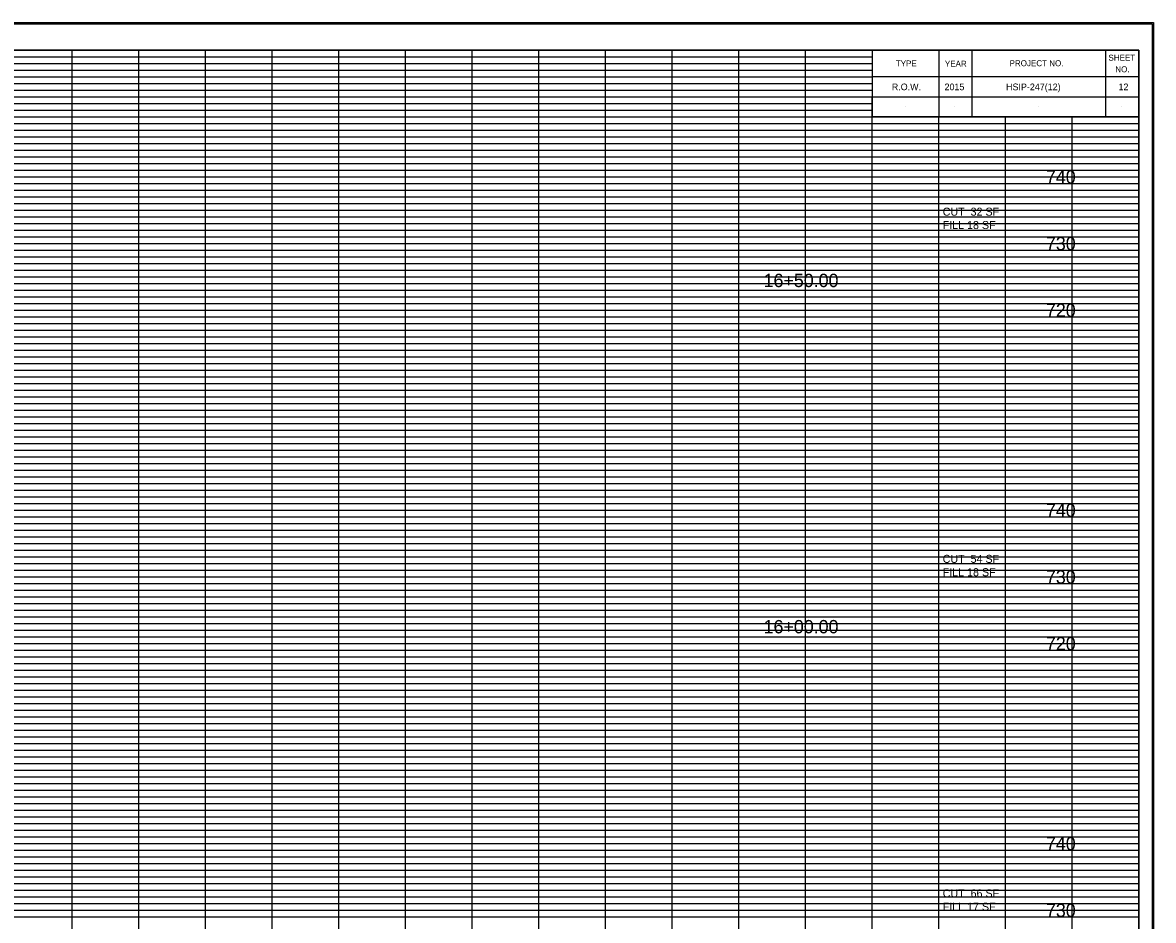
# Model space of a CAD drawing. Extents: x -200 to 1704, y -325 to 2307.
# Drawn here: x 1152.6 to 1322.2, y 1619.5 to 1754.1 of the extents above; entities that cross this region are included whole.
import ezdxf

# ---------------------------------------------------------------- set-up
doc = ezdxf.new("R2010")
doc.units = 0
for name, color, linetype in [('DESIGN - SCRATCH - User 1', 7, 'Continuous'), ('DESIGN - SHEET - Corner Text', 7, 'Continuous'), ('DESIGN - SHEET - Light Grid', 7, 'Continuous'), ('DESIGN - SHEET - Linework', 7, 'Continuous'), ('DESIGN - SHEET - Plot Shape', 7, 'Continuous'), ('DESIGN - TYPICAL - Text', 7, 'Continuous')]:
    doc.layers.add(name, color=color, linetype=linetype)

msp = doc.modelspace()

# ---------------------------------------------------------------- linework, layer by layer
at = {"layer": 'DESIGN - SCRATCH - User 1'}
for p, q in [((1285, 1744.5), (1285, 1744.5)), ((1292.4, 1744.5), (1292.4, 1744.5)), ((1304.9, 1744.5), (1304.9, 1744.5)), ((1317.4, 1744.5), (1317.4, 1744.5)), ((1285, 1741.5), (1285, 1741.5)), ((1292.4, 1741.5), (1292.4, 1741.5)), ((1304.9, 1741.5), (1304.9, 1741.5)), ((1317.4, 1741.5), (1317.4, 1741.5))]:
    msp.add_line(p, q, dxfattribs=at)
at = {"layer": 'DESIGN - SHEET - Light Grid'}
for p, q in [((1080, 1749), (1160, 1749)), ((1160, 1749), (1240, 1749)), ((1240, 1749), (1280, 1749)), ((1080, 1748), (1160, 1748)), ((1080, 1747), (1160, 1747)), ((1160, 1748), (1240, 1748)), ((1160, 1747), (1240, 1747)), ((1240, 1748), (1280, 1748)), ((1240, 1747), (1280, 1747)), ((1080, 1746), (1160, 1746)), ((1080, 1745), (1160, 1745)), ((1160, 1746), (1240, 1746)), ((1160, 1745), (1240, 1745)), ((1240, 1746), (1280, 1746)), ((1240, 1745), (1280, 1745)), ((1080, 1744), (1160, 1744)), ((1160, 1744), (1240, 1744)), ((1240, 1744), (1280, 1744)), ((1080, 1743), (1160, 1743)), ((1080, 1742), (1160, 1742)), ((1160, 1743), (1240, 1743)), ((1160, 1742), (1240, 1742)), ((1240, 1743), (1280, 1743)), ((1240, 1742), (1280, 1742)), ((1080, 1741), (1160, 1741)), ((1160, 1741), (1240, 1741)), ((1240, 1741), (1280, 1741)), ((1080, 1739), (1160, 1739)), ((1160, 1739), (1240, 1739)), ((1240, 1739), (1320, 1739)), ((1080, 1738), (1160, 1738)), ((1080, 1737), (1160, 1737)), ((1160, 1738), (1240, 1738)), ((1160, 1737), (1240, 1737)), ((1240, 1738), (1320, 1738)), ((1240, 1737), (1320, 1737)), ((1080, 1736), (1160, 1736)), ((1080, 1735), (1160, 1735)), ((1160, 1736), (1240, 1736)), ((1160, 1735), (1240, 1735)), ((1240, 1736), (1320, 1736)), ((1240, 1735), (1320, 1735)), ((1080, 1734), (1160, 1734)), ((1160, 1734), (1240, 1734)), ((1240, 1734), (1320, 1734)), ((1080, 1733), (1160, 1733)), ((1080, 1732), (1160, 1732)), ((1160, 1733), (1240, 1733)), ((1160, 1732), (1240, 1732)), ((1240, 1733), (1320, 1733)), ((1240, 1732), (1320, 1732)), ((1080, 1731), (1160, 1731)), ((1160, 1731), (1240, 1731)), ((1240, 1731), (1320, 1731)), ((1080, 1729), (1160, 1729)), ((1160, 1729), (1240, 1729)), ((1240, 1729), (1320, 1729)), ((1080, 1728), (1160, 1728)), ((1080, 1727), (1160, 1727)), ((1160, 1728), (1240, 1728)), ((1160, 1727), (1240, 1727)), ((1240, 1728), (1320, 1728)), ((1240, 1727), (1320, 1727)), ((1080, 1726), (1160, 1726)), ((1080, 1725), (1160, 1725)), ((1160, 1726), (1240, 1726)), ((1160, 1725), (1240, 1725)), ((1240, 1726), (1320, 1726)), ((1240, 1725), (1320, 1725)), ((1080, 1724), (1160, 1724)), ((1080, 1723), (1160, 1723)), ((1160, 1724), (1240, 1724)), ((1160, 1723), (1240, 1723)), ((1240, 1724), (1320, 1724)), ((1240, 1723), (1320, 1723)), ((1080, 1722), (1160, 1722)), ((1160, 1722), (1240, 1722)), ((1240, 1722), (1320, 1722)), ((1080, 1721), (1160, 1721)), ((1160, 1721), (1240, 1721)), ((1240, 1721), (1320, 1721)), ((1080, 1719), (1160, 1719)), ((1080, 1718), (1160, 1718)), ((1160, 1719), (1240, 1719)), ((1160, 1718), (1240, 1718)), ((1240, 1719), (1320, 1719)), ((1240, 1718), (1320, 1718)), ((1080, 1717), (1160, 1717)), ((1160, 1717), (1240, 1717)), ((1240, 1717), (1320, 1717)), ((1080, 1716), (1160, 1716)), ((1080, 1715), (1160, 1715)), ((1160, 1716), (1240, 1716)), ((1160, 1715), (1240, 1715)), ((1240, 1716), (1320, 1716)), ((1240, 1715), (1320, 1715)), ((1080, 1714), (1160, 1714)), ((1080, 1713), (1160, 1713)), ((1160, 1714), (1240, 1714)), ((1160, 1713), (1240, 1713)), ((1240, 1714), (1320, 1714)), ((1240, 1713), (1320, 1713)), ((1080, 1712), (1160, 1712)), ((1160, 1712), (1240, 1712)), ((1240, 1712), (1320, 1712)), ((1080, 1711), (1160, 1711)), ((1160, 1711), (1240, 1711)), ((1240, 1711), (1320, 1711)), ((1080, 1709), (1160, 1709)), ((1080, 1708), (1160, 1708)), ((1160, 1709), (1240, 1709)), ((1160, 1708), (1240, 1708)), ((1240, 1709), (1320, 1709)), ((1240, 1708), (1320, 1708)), ((1080, 1707), (1160, 1707)), ((1080, 1706), (1160, 1706)), ((1160, 1707), (1240, 1707)), ((1160, 1706), (1240, 1706)), ((1240, 1707), (1320, 1707)), ((1240, 1706), (1320, 1706)), ((1080, 1705), (1160, 1705)), ((1160, 1705), (1240, 1705)), ((1240, 1705), (1320, 1705)), ((1080, 1704), (1160, 1704)), ((1080, 1703), (1160, 1703)), ((1160, 1704), (1240, 1704)), ((1160, 1703), (1240, 1703)), ((1240, 1704), (1320, 1704)), ((1240, 1703), (1320, 1703)), ((1080, 1702), (1160, 1702)), ((1080, 1701), (1160, 1701)), ((1160, 1702), (1240, 1702)), ((1160, 1701), (1240, 1701)), ((1240, 1702), (1320, 1702)), ((1240, 1701), (1320, 1701)), ((1080, 1699), (1160, 1699)), ((1080, 1698), (1160, 1698)), ((1160, 1699), (1240, 1699)), ((1160, 1698), (1240, 1698)), ((1240, 1699), (1320, 1699)), ((1240, 1698), (1320, 1698)), ((1080, 1697), (1160, 1697)), ((1080, 1696), (1160, 1696)), ((1160, 1697), (1240, 1697)), ((1160, 1696), (1240, 1696)), ((1240, 1697), (1320, 1697)), ((1240, 1696), (1320, 1696)), ((1080, 1695), (1160, 1695)), ((1160, 1695), (1240, 1695)), ((1240, 1695), (1320, 1695)), ((1080, 1694), (1160, 1694)), ((1080, 1693), (1160, 1693)), ((1160, 1694), (1240, 1694)), ((1160, 1693), (1240, 1693)), ((1240, 1694), (1320, 1694)), ((1240, 1693), (1320, 1693)), ((1080, 1692), (1160, 1692)), ((1080, 1691), (1160, 1691)), ((1160, 1692), (1240, 1692)), ((1160, 1691), (1240, 1691)), ((1240, 1692), (1320, 1692)), ((1240, 1691), (1320, 1691)), ((1080, 1689), (1160, 1689)), ((1080, 1688), (1160, 1688)), ((1160, 1689), (1240, 1689)), ((1160, 1688), (1240, 1688)), ((1240, 1689), (1320, 1689)), ((1240, 1688), (1320, 1688)), ((1080, 1687), (1160, 1687)), ((1080, 1686), (1160, 1686)), ((1160, 1687), (1240, 1687)), ((1160, 1686), (1240, 1686)), ((1240, 1687), (1320, 1687)), ((1240, 1686), (1320, 1686)), ((1080, 1685), (1160, 1685)), ((1080, 1684), (1160, 1684)), ((1160, 1685), (1240, 1685)), ((1160, 1684), (1240, 1684)), ((1240, 1685), (1320, 1685)), ((1240, 1684), (1320, 1684)), ((1080, 1683), (1160, 1683)), ((1160, 1683), (1240, 1683)), ((1240, 1683), (1320, 1683)), ((1080, 1682), (1160, 1682)), ((1080, 1681), (1160, 1681)), ((1160, 1682), (1240, 1682)), ((1160, 1681), (1240, 1681)), ((1240, 1682), (1320, 1682)), ((1240, 1681), (1320, 1681)), ((1080, 1679), (1160, 1679)), ((1160, 1679), (1240, 1679)), ((1240, 1679), (1320, 1679)), ((1080, 1678), (1160, 1678)), ((1160, 1678), (1240, 1678)), ((1240, 1678), (1320, 1678)), ((1080, 1677), (1160, 1677)), ((1080, 1676), (1160, 1676)), ((1160, 1677), (1240, 1677)), ((1160, 1676), (1240, 1676)), ((1240, 1677), (1320, 1677)), ((1240, 1676), (1320, 1676)), ((1080, 1675), (1160, 1675)), ((1080, 1674), (1160, 1674)), ((1160, 1675), (1240, 1675)), ((1160, 1674), (1240, 1674)), ((1240, 1675), (1320, 1675)), ((1240, 1674), (1320, 1674)), ((1080, 1673), (1160, 1673)), ((1160, 1673), (1240, 1673)), ((1240, 1673), (1320, 1673)), ((1080, 1672), (1160, 1672)), ((1080, 1671), (1160, 1671)), ((1160, 1672), (1240, 1672)), ((1160, 1671), (1240, 1671)), ((1240, 1672), (1320, 1672)), ((1240, 1671), (1320, 1671)), ((1080, 1669), (1160, 1669)), ((1160, 1669), (1240, 1669)), ((1240, 1669), (1320, 1669)), ((1080, 1668), (1160, 1668)), ((1080, 1667), (1160, 1667)), ((1160, 1668), (1240, 1668)), ((1160, 1667), (1240, 1667)), ((1240, 1668), (1320, 1668)), ((1240, 1667), (1320, 1667)), ((1080, 1666), (1160, 1666)), ((1160, 1666), (1240, 1666)), ((1240, 1666), (1320, 1666)), ((1080, 1665), (1160, 1665)), ((1080, 1664), (1160, 1664)), ((1160, 1665), (1240, 1665)), ((1160, 1664), (1240, 1664)), ((1240, 1665), (1320, 1665)), ((1240, 1664), (1320, 1664)), ((1080, 1663), (1160, 1663)), ((1080, 1662), (1160, 1662)), ((1160, 1663), (1240, 1663)), ((1160, 1662), (1240, 1662)), ((1240, 1663), (1320, 1663)), ((1240, 1662), (1320, 1662)), ((1080, 1661), (1160, 1661)), ((1160, 1661), (1240, 1661)), ((1240, 1661), (1320, 1661)), ((1080, 1659), (1160, 1659)), ((1160, 1659), (1240, 1659)), ((1240, 1659), (1320, 1659)), ((1080, 1658), (1160, 1658)), ((1080, 1657), (1160, 1657)), ((1160, 1658), (1240, 1658)), ((1160, 1657), (1240, 1657)), ((1240, 1658), (1320, 1658)), ((1240, 1657), (1320, 1657)), ((1080, 1656), (1160, 1656)), ((1160, 1656), (1240, 1656)), ((1240, 1656), (1320, 1656)), ((1080, 1655), (1160, 1655)), ((1080, 1654), (1160, 1654)), ((1160, 1655), (1240, 1655)), ((1160, 1654), (1240, 1654)), ((1240, 1655), (1320, 1655)), ((1240, 1654), (1320, 1654)), ((1080, 1653), (1160, 1653)), ((1080, 1652), (1160, 1652)), ((1160, 1653), (1240, 1653)), ((1160, 1652), (1240, 1652)), ((1240, 1653), (1320, 1653)), ((1240, 1652), (1320, 1652)), ((1080, 1651), (1160, 1651)), ((1160, 1651), (1240, 1651)), ((1240, 1651), (1320, 1651)), ((1080, 1649), (1160, 1649)), ((1160, 1649), (1240, 1649)), ((1240, 1649), (1320, 1649)), ((1080, 1648), (1160, 1648)), ((1080, 1647), (1160, 1647)), ((1160, 1648), (1240, 1648)), ((1160, 1647), (1240, 1647)), ((1240, 1648), (1320, 1648)), ((1240, 1647), (1320, 1647)), ((1080, 1646), (1160, 1646)), ((1080, 1645), (1160, 1645)), ((1160, 1646), (1240, 1646)), ((1160, 1645), (1240, 1645)), ((1240, 1646), (1320, 1646)), ((1240, 1645), (1320, 1645)), ((1080, 1644), (1160, 1644)), ((1160, 1644), (1240, 1644)), ((1240, 1644), (1320, 1644)), ((1080, 1643), (1160, 1643)), ((1080, 1642), (1160, 1642)), ((1160, 1643), (1240, 1643)), ((1160, 1642), (1240, 1642)), ((1240, 1643), (1320, 1643)), ((1240, 1642), (1320, 1642)), ((1080, 1641), (1160, 1641)), ((1160, 1641), (1240, 1641)), ((1240, 1641), (1320, 1641)), ((1080, 1639), (1160, 1639)), ((1160, 1639), (1240, 1639)), ((1240, 1639), (1320, 1639)), ((1080, 1638), (1160, 1638)), ((1080, 1637), (1160, 1637)), ((1160, 1638), (1240, 1638)), ((1160, 1637), (1240, 1637)), ((1240, 1638), (1320, 1638)), ((1240, 1637), (1320, 1637)), ((1080, 1636), (1160, 1636)), ((1080, 1635), (1160, 1635)), ((1160, 1636), (1240, 1636)), ((1160, 1635), (1240, 1635)), ((1240, 1636), (1320, 1636)), ((1240, 1635), (1320, 1635)), ((1080, 1634), (1160, 1634)), ((1160, 1634), (1240, 1634)), ((1240, 1634), (1320, 1634)), ((1080, 1633), (1160, 1633)), ((1080, 1632), (1160, 1632)), ((1160, 1633), (1240, 1633)), ((1160, 1632), (1240, 1632)), ((1240, 1633), (1320, 1633)), ((1240, 1632), (1320, 1632)), ((1080, 1631), (1160, 1631)), ((1160, 1631), (1240, 1631)), ((1240, 1631), (1320, 1631)), ((1080, 1629), (1160, 1629)), ((1080, 1628), (1160, 1628)), ((1160, 1629), (1240, 1629)), ((1160, 1628), (1240, 1628)), ((1240, 1629), (1320, 1629)), ((1240, 1628), (1320, 1628)), ((1080, 1627), (1160, 1627)), ((1160, 1627), (1240, 1627)), ((1240, 1627), (1320, 1627)), ((1080, 1626), (1160, 1626)), ((1080, 1625), (1160, 1625)), ((1160, 1626), (1240, 1626)), ((1160, 1625), (1240, 1625)), ((1240, 1626), (1320, 1626)), ((1240, 1625), (1320, 1625)), ((1080, 1624), (1160, 1624)), ((1080, 1623), (1160, 1623)), ((1160, 1624), (1240, 1624)), ((1160, 1623), (1240, 1623)), ((1240, 1624), (1320, 1624)), ((1240, 1623), (1320, 1623)), ((1080, 1622), (1160, 1622)), ((1160, 1622), (1240, 1622)), ((1240, 1622), (1320, 1622)), ((1080, 1621), (1160, 1621)), ((1160, 1621), (1240, 1621)), ((1240, 1621), (1320, 1621))]:
    msp.add_line(p, q, dxfattribs=at)
at = {"layer": 'DESIGN - SHEET - Linework'}
for p, q in [((981.77, 1754.14), (1322.17, 1754.14)), ((1322.17, 1754.14), (1322.17, 1535.86)), ((1160, 1540), (1160, 1750)), ((1170, 1540), (1170, 1750)), ((1180, 1540), (1180, 1750)), ((1190, 1540), (1190, 1750)), ((1200, 1540), (1200, 1750)), ((1210, 1540), (1210, 1750)), ((1220, 1540), (1220, 1750)), ((1230, 1540), (1230, 1750)), ((1240, 1540), (1240, 1750)), ((1250, 1540), (1250, 1750)), ((1260, 1540), (1260, 1750)), ((1270, 1540), (1270, 1750)), ((1000, 1740), (1280, 1740)), ((1280, 1540), (1280, 1740)), ((1290, 1540), (1290, 1740)), ((1300, 1540), (1300, 1740)), ((1310, 1540), (1310, 1740)), ((1000, 1730), (1320, 1730)), ((1000, 1720), (1320, 1720)), ((1000, 1710), (1320, 1710)), ((1000, 1700), (1320, 1700)), ((1000, 1690), (1320, 1690)), ((1000, 1680), (1320, 1680)), ((1000, 1670), (1320, 1670)), ((1000, 1660), (1320, 1660)), ((1000, 1650), (1320, 1650)), ((1000, 1640), (1320, 1640)), ((1000, 1630), (1320, 1630)), ((1000, 1620), (1320, 1620))]:
    msp.add_line(p, q, dxfattribs=at)
for points in [[(1000, 1750), (1000, 1540), (1320, 1540), (1320, 1750), (1000, 1750)], [(1280, 1750), (1280, 1740), (1320, 1740), (1320, 1750), (1315, 1750), (1315, 1740), (1295, 1740), (1295, 1750), (1290, 1750), (1290, 1740), (1320, 1740), (1280, 1740), (1280, 1743), (1320, 1743), (1320, 1746), (1280, 1746)]]:
    msp.add_lwpolyline(points, dxfattribs=at)
at = {"layer": 'DESIGN - SHEET - Plot Shape'}
for points in [[(981.97, 1753.94), (1321.97, 1753.94), (1321.97, 1536.06), (981.97, 1536.06)], [(991.5, 1750), (1320, 1750), (1320, 1537.5), (991.5, 1537.5)]]:
    msp.add_lwpolyline(points, close=True, dxfattribs=at)

# ---------------------------------------------------------------- texts
at = {"layer": 'DESIGN - SHEET - Corner Text'}
for s, height, p in [('TYPE', 0.9, (1283.54, 1747.56)), ('YEAR', 0.9, (1290.9, 1747.52)), ('PROJECT NO.', 0.9, (1300.6, 1747.6)), ('SHEET', 0.9, (1315.43, 1748.43)), ('NO.', 0.9, (1316.46, 1746.69)), ('R.O.W.', 1, (1282.94, 1744)), ('2015', 1, (1290.85, 1744)), ('HSIP-247(12)', 1, (1300.08, 1744)), ('12', 1, (1316.94, 1744))]:
    msp.add_text(s, height=height, dxfattribs=at).set_placement(p)
at = {"layer": 'DESIGN - TYPICAL - Text'}
for s, height, p in [('     740     ', 2, (1302.34, 1730)), ('CUT  32 SF', 1.2, (1290.57, 1725.18)), ('FILL 18 SF', 1.2, (1290.57, 1723.18)), ('     730     ', 2, (1302.34, 1720)), ('     16+50.00     ', 2, (1260, 1714.47)), ('     720     ', 2, (1302.34, 1710)), ('     740     ', 2, (1302.34, 1680)), ('CUT  54 SF', 1.2, (1290.57, 1673.11)), ('FILL 18 SF', 1.2, (1290.57, 1671.11)), ('     730     ', 2, (1302.34, 1670)), ('     16+00.00     ', 2, (1260, 1662.54)), ('     720     ', 2, (1302.34, 1660)), ('     740     ', 2, (1302.34, 1630)), ('CUT  66 SF', 1.2, (1290.57, 1622.94)), ('FILL 17 SF', 1.2, (1290.57, 1620.94)), ('     730     ', 2, (1302.34, 1620))]:
    msp.add_text(s, height=height, dxfattribs=at).set_placement(p)

doc.saveas('drawing.dxf')
